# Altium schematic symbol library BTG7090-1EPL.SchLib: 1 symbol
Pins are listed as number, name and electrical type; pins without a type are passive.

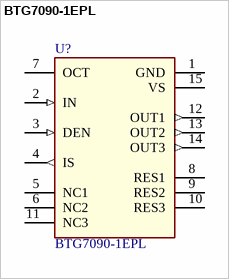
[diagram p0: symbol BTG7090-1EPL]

## BTG7090-1EPL
designator U?
PROFET Load Guard, Smart High-Side Power Switch; Manufacturer: Infineon Technologies
pins: 1 GND (power) "Ground", 2 IN (in) "Input Channel", 3 DEN (in) "Diagnostic Enable", 4 IS (out) "SENSE current output", 5 NC1 "Not connected", 6 NC2 "Not connected", 7 OCT "Adjustable overcurrent threshold", 8 RES1 "Reserved 1", 9 RES2 "Reserved 2", 10 RES3 "Reserved 3", 11 NC3 "Not Connected", 12 OUT1 (out) "Output 1", 13 OUT2 (out) "Output 2", 14 OUT3 (out) "Output 3", 15 VS (power) "Supply Voltage"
